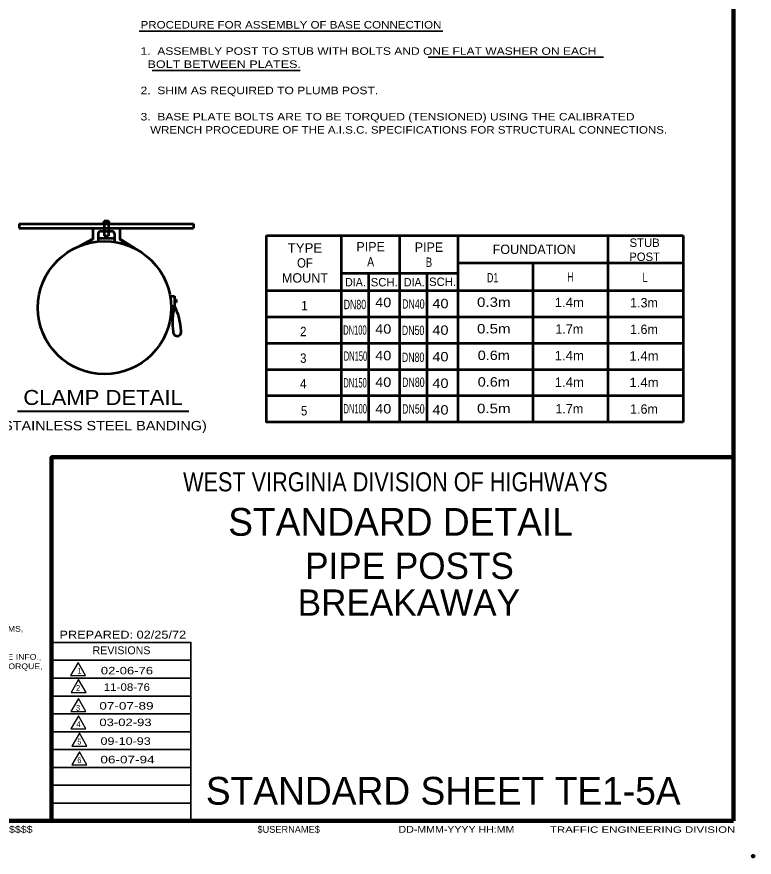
# Model space of a CAD drawing. Extents: x 11 to 867, y -284 to 260.
# Drawn here: x 630.9 to 866.6, y -283.7 to -14.9 of the extents above; entities that cross this region are included whole.
import ezdxf
from ezdxf.enums import TextEntityAlignment as Align

# ---------------------------------------------------------------- set-up
doc = ezdxf.new("R2010")
doc.units = 0
doc.header["$LTSCALE"] = 1.2
doc.header["$PDMODE"] = 32
doc.header["$PDSIZE"] = 0.6
doc.layers.add('1', color=7, linetype='Continuous', lineweight=53)
doc.layers.add('61', color=7, linetype='Continuous', lineweight=35)

msp = doc.modelspace()

# ---------------------------------------------------------------- linework, layer by layer
at = {"layer": '1', "lineweight": 158}
for q in [(860.008, 254), (860.008, -155.8), (68.408, -272.101)]:
    msp.add_line((860.008, -272.101), q, dxfattribs=at)
at = {"layer": '1', "lineweight": 13}
msp.add_line((860.008, -272.101), (860.008, 254), dxfattribs=at)
at = {"layer": '1', "lineweight": 35}
for p, q in [((670.017, -19.522), (767.019, -19.522)), ((762.397, -27.87), (818.398, -27.87)), ((674.124, -32.132), (721.484, -32.132)), ((686.508, -220.701), (642.008, -220.701)), ((686.508, -226.401), (642.008, -226.401)), ((686.508, -232.201), (642.008, -232.201)), ((686.508, -237.901), (642.008, -237.901)), ((686.508, -243.601), (642.008, -243.601)), ((686.508, -249.3), (642.008, -249.3)), ((686.508, -255.001), (642.008, -255.001)), ((686.508, -260.701), (642.008, -260.701)), ((686.508, -266.401), (642.008, -266.401))]:
    msp.add_line(p, q, dxfattribs=at)
at = {"layer": '1'}
for p, q in [((658.794, -80.195), (660.234, -80.195)), ((658.794, -80.195), (658.794, -80.831)), ((660.234, -80.195), (660.234, -80.831)), ((631.644, -81.189), (687.382, -81.189)), ((631.644, -81.189), (631.644, -82.497)), ((631.644, -82.497), (687.382, -82.497)), ((655.194, -82.497), (655.194, -86.149)), ((658.314, -80.831), (660.714, -80.831)), ((658.314, -80.831), (658.314, -81.189)), ((658.794, -80.831), (658.794, -84.949)), ((660.234, -80.831), (660.234, -84.949)), ((660.714, -80.831), (660.714, -81.189)), ((663.834, -82.497), (663.834, -86.149)), ((687.382, -81.189), (687.382, -82.497)), ((651.06, -88.183), (655.194, -85.969)), ((656.874, -84.251), (656.874, -86.781)), ((656.878, -85.673), (662.154, -85.673)), ((657.834, -83.531), (661.194, -83.531)), ((658.794, -84.949), (660.234, -84.949)), ((662.154, -84.251), (662.154, -86.933)), ((668.68, -89.061), (663.834, -85.961)), ((734.657, -144.598), (734.657, -84.844)), ((753.255, -84.844), (753.255, -144.598)), ((771.853, -84.844), (771.853, -144.598)), ((819.853, -84.844), (819.853, -144.598)), ((654.474, -86.535), (655.194, -86.149)), ((654.474, -86.535), (654.474, -87.149)), ((664.554, -86.535), (663.834, -86.149)), ((664.554, -86.535), (664.554, -87.447)), ((843.853, -93.72), (771.853, -93.72)), ((795.853, -93.72), (795.853, -144.598)), ((743.356, -96.924), (743.356, -144.598)), ((761.955, -96.924), (761.955, -144.598)), ((679.858, -104.269), (681.33, -104.269)), ((681.33, -104.269), (681.33, -107.445)), ((843.853, -102.598), (710.657, -102.598)), ((680.174, -107.445), (681.33, -107.445)), ((681.81, -105.377), (681.33, -105.377)), ((681.81, -106.337), (681.33, -106.337)), ((681.81, -105.377), (681.81, -106.337)), ((843.853, -110.998), (710.657, -110.998)), ((843.853, -119.398), (710.657, -119.398)), ((843.853, -127.798), (710.657, -127.798)), ((843.853, -136.198), (710.657, -136.198))]:
    msp.add_line(p, q, dxfattribs=at)
at = {"layer": '1', "lineweight": 40}
msp.add_line((631.087, -141.104), (685.85, -141.104), dxfattribs=at)
at = {"layer": '1'}
for points in [[(843.853, -144.598), (710.657, -144.598), (710.657, -84.844)], [(710.657, -84.844), (734.657, -84.844), (771.853, -84.844), (843.853, -84.844)], [(843.853, -84.844), (843.853, -102.598), (843.853, -144.598)], [(734.657, -96.924), (753.255, -96.924), (771.853, -96.924)]]:
    msp.add_lwpolyline(points, dxfattribs=at)
at = {"layer": '1', "lineweight": 158}
msp.add_lwpolyline([(642.008, -272.101), (642.008, -155.8), (860.008, -155.8)], dxfattribs=at)
at = {"layer": '1', "lineweight": 35}
msp.add_lwpolyline([(686.508, -272.101), (686.508, -215.001), (642.008, -215.001)], dxfattribs=at)
at = {"layer": '1', "lineweight": 25}
for points in [[(650.467, -221.391), (648.067, -225.548), (652.867, -225.548)], [(650.608, -226.896), (648.208, -231.053), (653.008, -231.053)], [(650.592, -232.965), (648.192, -237.122), (652.992, -237.122)], [(650.562, -238.47), (648.162, -242.627), (652.962, -242.627)], [(650.878, -244.062), (648.478, -248.219), (653.278, -248.219)], [(650.889, -249.98), (648.49, -254.137), (653.289, -254.137)]]:
    msp.add_lwpolyline(points, close=True, dxfattribs=at)
at = {"layer": '1'}
msp.add_circle((658.906, -107.956), 21.273, dxfattribs=at)
for centre, radius, start, end in [((657.817, -84.507), 0.977, 88.95712, 164.78268), ((661.212, -84.507), 0.977, 15.21732, 91.04288), ((699.544, -112.677), 18.95, 163.97175, 189.25477), ((665.167, -115.811), 18.201, 1.04068, 27.36708), ((682.117, -115.754), 1.277, 178.67702, 12.36646)]:
    msp.add_arc(centre, radius, start, end, dxfattribs=at)
msp.add_point((866.308, -283.401), dxfattribs=at)
at = {"layer": '61', "lineweight": 53}
for q in [(707.308, -272.101), (707.308, -272.101), (707.308, -272.101), (707.608, -272.101), (707.608, -272.101)]:
    msp.add_line((860.008, -272.101), q, dxfattribs=at)

# ---------------------------------------------------------------- texts
at = {"layer": '1'}
for s, height, width, p in [('PROCEDURE FOR ASSEMBLY OF BASE CONNECTION', 2.4, 1.15, (670.437, -18.682)), ('1.  ASSEMBLY POST TO STUB WITH BOLTS AND ONE FLAT WASHER ON EACH', 2.4, 1.2, (670.437, -27.082)), ('  BOLT BETWEEN PLATES.', 2.4, 1.25, (670.437, -31.282)), ('2.  SHIM AS REQUIRED TO PLUMB POST.', 2.4, 1.2, (670.437, -39.682)), ('3.  BASE PLATE BOLTS ARE TO BE TORQUED (TENSIONED) USING THE CALIBRATED', 2.4, 1.2, (670.437, -48.082)), ('   WRENCH PROCEDURE OF THE A.I.S.C. SPECIFICATIONS FOR STRUCTURAL CONNECTIONS.', 2.4, 1.15, (670.437, -52.282)), ('MAX. LOAD, TYPE 4 CROSS-ARMS,', 1.8, 1.15, (586.48, -211.554)), ('PREPARED: 02/25/72', 2.537, 1.2, (644.508, -213.8)), ("ADDED 9' NOTE, KEEPER PLATE INFO.,", 1.8, 1.15, (586.48, -220.554)), ('REVISED H.S. BOLTS NOTES, TORQUE,', 1.8, 1.15, (586.48, -223.554)), ('$$$$$$$$$FILENAME$$$$$$$$', 2.2, 1.15, (587.008, -275.901)), ('DD-MMM-YYYY HH:MM', 2.2, 1.15, (752.908, -275.901)), ('TRAFFIC ENGINEERING DIVISION', 2.031, 1.35, (801.308, -275.901))]:
    msp.add_text(s, height=height, dxfattribs=dict(at, width=width)).set_placement(p)
for s, height, p in [('STUB', 2.7, (831.588, -88.529)), ('PIPE', 3, (743.995, -89.974)), ('PIPE', 3, (762.643, -90.105)), ('FOUNDATION', 3, (796.262, -90.797)), ('POST', 2.7, (831.587, -93.029)), ('MOUNT', 3, (722.983, -99.932)), ('SCH.', 2.7, (748.328, -101.156)), ('SCH.', 2.7, (766.976, -101.025)), ('1', 3, (722.835, -108.794)), ('1.3m', 3, (831.387, -107.869)), ('1.7m', 3, (807.506, -116.28)), ('1.6m', 3, (831.387, -116.369)), ('1.7m', 3, (807.506, -141.78)), ('1.6m', 3, (831.387, -141.869)), ('STANDARD DETAIL', 8.881, (753.558, -180.901)), ('PIPE POSTS', 8.391, (756.407, -194.699)), ('BREAKAWAY', 8.391, (756.207, -206.472)), ('1', 1.8, (650.929, -224.973))]:
    msp.add_text(s, height=height, dxfattribs=at).set_placement(p, align=Align.CENTER)
for s, height, width, p in [('TYPE', 3, 1.05, (722.983, -90.332)), ('OF', 3, 0.9, (722.983, -95.132)), ('A', 3, 0.85, (743.995, -94.773)), ('B', 3, 0.75, (762.643, -94.905)), ('H', 3, 0.7, (807.818, -99.599)), ('L', 3, 0.75, (831.719, -99.73)), ('DIA.', 2.7, 0.95, (739.136, -101.156)), ('DIA.', 2.7, 0.95, (757.915, -101.156)), ('D1', 3, 0.7, (782.998, -99.861)), ('40', 3, 1.15, (748.022, -107.774)), ('0.3m', 3, 1.2, (783.358, -107.692)), ('1.4m', 3, 1.05, (807.506, -107.78)), ('DN80', 3, 0.7, (738.966, -108.435)), ('DN40', 3, 0.7, (757.654, -108.263)), ('40', 3, 1.15, (766.31, -108.129)), ('2', 3, 0.9, (722.458, -117.07)), ('DN100', 3, 0.6, (738.966, -116.605)), ('40', 3, 1.15, (748.022, -116.274)), ('DN50', 3, 0.7, (757.565, -116.699)), ('40', 3, 1.15, (766.31, -116.629)), ('0.5m', 3, 1.2, (783.358, -116.192)), ('3', 3, 0.9, (722.458, -125.609)), ('DN150', 3, 0.6, (739.144, -124.952)), ('40', 3, 1.15, (748.022, -124.774)), ('DN80', 3, 0.7, (757.565, -125.312)), ('40', 3, 1.15, (766.31, -125.129)), ('0.6m', 3, 1.15, (783.358, -124.692)), ('1.4m', 3, 1.05, (807.506, -124.78)), ('1.4m', 3, 1.05, (831.387, -124.869)), ('4', 3, 0.95, (722.458, -133.754)), ('DN150', 3, 0.6, (739.011, -133.477)), ('40', 3, 1.15, (748.022, -133.274)), ('DN80', 3, 0.7, (757.654, -133.305)), ('40', 3, 1.15, (766.31, -133.629)), ('0.6m', 3, 1.15, (783.358, -133.192)), ('1.4m', 3, 1.05, (807.506, -133.28)), ('1.4m', 3, 1.05, (831.387, -133.369)), ('CLAMP DETAIL', 4.8, 1.1, (658.455, -139.071)), ('5', 3, 0.9, (722.72, -142.424)), ('DN100', 3, 0.6, (739.055, -141.779)), ('40', 3, 1.15, (748.022, -141.774)), ('DN50', 3, 0.7, (757.654, -141.829)), ('40', 3, 1.15, (766.31, -142.129)), ('0.5m', 3, 1.2, (783.358, -141.692)), ('(STAINLESS STEEL BANDING)', 3, 1.15, (658.278, -147.182)), ('WEST VIRGINIA DIVISION OF HIGHWAYS', 6.089, 0.85, (751.908, -166.701)), ('02-06-76', 2.4, 1.3, (666.083, -225.233)), ('11-08-76', 2.4, 1.15, (666.059, -230.513)), ('2', 1.8, 0.9, (650.467, -230.478)), ('3', 1.8, 0.9, (650.451, -236.829)), ('07-07-89', 2.4, 1.35, (665.926, -236.498)), ('4', 1.8, 0.95, (650.561, -242.052)), ('03-02-93', 2.4, 1.3, (665.613, -241.778)), ('5', 1.8, 0.9, (650.878, -247.645)), ('09-10-93', 2.4, 1.25, (665.656, -247.767)), ('6', 1.8, 0.85, (650.889, -253.562)), ('06-07-94', 2.4, 1.35, (666.262, -253.677))]:
    msp.add_text(s, height=height, dxfattribs=dict(at, width=width)).set_placement(p, align=Align.CENTER)
for s, height, p in [('REVISIONS', 2.537, (655.108, -218.8)), ('STANDARD SHEET TE1-5A', 8.881, (691.308, -266.901)), ('$USERNAME$', 2.2, (707.808, -275.901))]:
    msp.add_text(s, height=height, dxfattribs=at).set_placement(p)

doc.saveas('drawing.dxf')
